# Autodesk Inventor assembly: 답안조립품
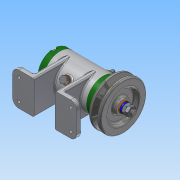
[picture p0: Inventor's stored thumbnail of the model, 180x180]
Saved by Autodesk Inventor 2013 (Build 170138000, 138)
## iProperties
Created: 2017-02
Part Number: 답안조립품
Document SubType Name: Assembly
Designer: Administrator
Author: Administrator
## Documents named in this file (16)
- C:\Users\Administrator\Desktop\470208V1006\답안조립품.iam
- C:\Users\Administrator\Desktop\470208V1006\V벨트풀리.ipt
- C:\Users\Administrator\Desktop\470208V1006\너트 M 8.ipt
- C:\Users\Administrator\Desktop\470208V1006\니플 M 6 x 0.75.ipt
- C:\Users\Administrator\Desktop\470208V1006\뒤커버.ipt
- C:\Users\Administrator\Desktop\470208V1006\베어링 15 x 32 x 9.ipt
- C:\Users\Administrator\Desktop\470208V1006\본체.ipt
- C:\Users\Administrator\Desktop\470208V1006\볼트 M 6 x 8.ipt
- C:\Users\Administrator\Desktop\470208V1006\볼트 M4 x 12.ipt
- C:\Users\Administrator\Desktop\470208V1006\스프링와셔 8.ipt
- C:\Users\Administrator\Desktop\470208V1006\앞커버.ipt
- C:\Users\Administrator\Desktop\470208V1006\오일 실 15 25 7.ipt
- C:\Users\Administrator\Desktop\470208V1006\와셔 6x11.5.ipt
- C:\Users\Administrator\Desktop\470208V1006\와셔 8x17.ipt
- C:\Users\Administrator\Desktop\470208V1006\축.ipt
- C:\Users\Administrator\Desktop\470208V1006\키 3 x 3 x 12.ipt
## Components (11 placed, 3 different names)
1. V벨트풀리:1
2. KS B 2023 6002 - 15 x 32 x 9:1
3. KS B 2023 6002 - 15 x 32 x 9:2
4. ISO 4762 M4 x 12:5
5. ISO 4762 M4 x 12:6
6. ISO 4762 M4 x 12:7
7. ISO 4762 M4 x 12:8
8. ISO 4762 M4 x 12:1
9. ISO 4762 M4 x 12:2
10. ISO 4762 M4 x 12:3
11. ISO 4762 M4 x 12:4
